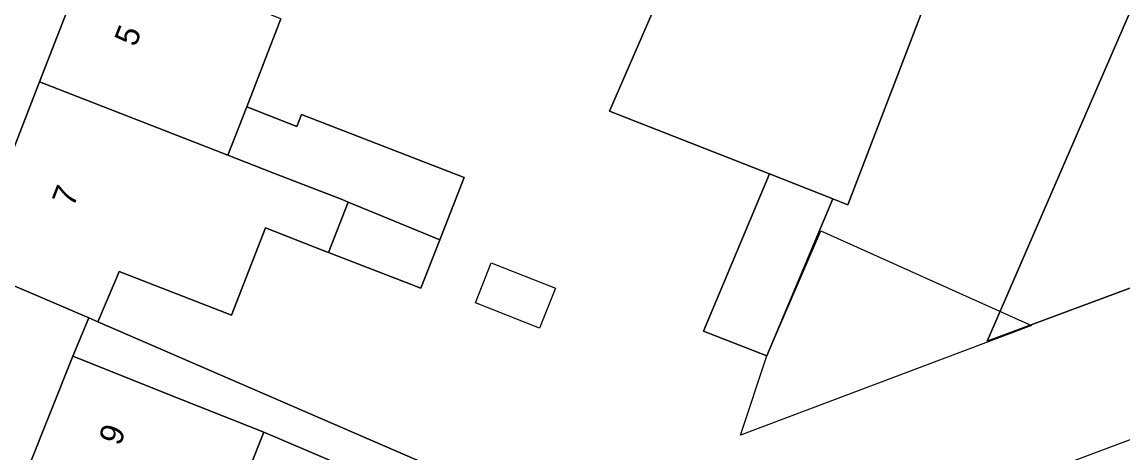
# Model space of a CAD drawing. Extents: x 161798 to 162385, y 382315 to 382833.
# Drawn here: x 162189.17 to 162235.92, y 382570.82 to 382589.12 of the extents above; entities that cross this region are included whole.
import ezdxf

# ---------------------------------------------------------------- set-up
doc = ezdxf.new("R2010")
doc.units = 0
for name, color, linetype in [('IMGEO_Erf', 7, 'Continuous'), ('IMGEO_Pand', 7, 'Continuous'), ('IMGEO_Pand_nummerreeks', 7, 'Continuous'), ('IMGEO_Pand_vergunning_verleend', 7, 'Continuous'), ('IMGEO_Voetpad_open', 7, 'Continuous')]:
    doc.layers.add(name, color=color, linetype=linetype)

msp = doc.modelspace()

# ---------------------------------------------------------------- linework, layer by layer
at = {"layer": 'IMGEO_Erf'}
for points in [[(162239.564, 382579.067), (162230.156, 382575.563), (162238.632, 382595.119), (162235.65, 382596.412), (162237.101, 382599.761)], [(162200.163, 382589.258), (162198.709, 382585.516), (162200.84, 382584.689), (162201.036, 382585.195), (162207.94, 382582.514), (162206.909, 382579.875), (162206.102, 382577.812), (162202.18, 382579.336), (162201.962, 382579.421), (162199.507, 382580.375), (162198.066, 382576.668), (162193.297, 382578.521), (162193.239, 382578.387), (162193.08, 382578.017), (162192.384, 382576.394), (162209.772, 382568.862)], [(162207.999, 382568.054), (162199.431, 382571.699), (162197.495, 382566.833)]]:
    msp.add_lwpolyline(points, dxfattribs=at)
msp.add_lwpolyline([(162220.802, 382574.936), (162218.113, 382575.994), (162220.912, 382582.668), (162214.119, 382585.338), (162217.707, 382593.617), (162218.951, 382596.487), (162224.575, 382594.142), (162225.75, 382596.93), (162229.557, 382595.219), (162227.423, 382589.653), (162224.244, 382581.359), (162223.602, 382581.611)], close=True, dxfattribs=at)
at = {"layer": 'IMGEO_Pand'}
for points in [[(162240.534, 382608.284), (162236.893, 382599.851), (162237.101, 382599.761), (162235.65, 382596.412), (162238.632, 382595.119), (162230.156, 382575.563), (162239.564, 382579.067), (162245.276, 382592.24), (162246.707, 382595.54), (162246.525, 382595.619), (162250.193, 382604.115)], [(162223.602, 382581.611), (162224.244, 382581.359), (162227.423, 382589.653), (162217.707, 382593.617), (162214.119, 382585.338), (162220.912, 382582.668)], [(162200.163, 382589.258), (162198.47, 382589.917), (162193.809, 382591.727), (162192.158, 382592.368), (162189.907, 382586.575), (162197.912, 382583.464), (162198.709, 382585.516)], [(162202.18, 382579.336), (162203.015, 382581.474), (162202.76, 382581.579), (162199.819, 382582.722), (162197.912, 382583.464), (162189.907, 382586.575), (162186.87, 382578.758), (162192.01, 382576.554), (162192.384, 382576.394), (162193.08, 382578.017), (162193.239, 382578.387), (162193.297, 382578.521), (162198.066, 382576.668), (162199.507, 382580.375), (162201.962, 382579.421)], [(162198.709, 382585.516), (162197.912, 382583.464), (162199.819, 382582.722), (162202.76, 382581.579), (162203.015, 382581.474), (162204.749, 382580.762), (162206.909, 382579.875), (162207.94, 382582.514), (162201.036, 382585.195), (162200.84, 382584.689)], [(162223.602, 382581.611), (162220.912, 382582.668), (162218.113, 382575.994), (162220.802, 382574.936)], [(162204.749, 382580.762), (162203.015, 382581.474), (162202.18, 382579.336), (162206.102, 382577.812), (162206.909, 382579.875)], [(162197.495, 382566.833), (162199.431, 382571.699), (162195.967, 382573.077), (162191.32, 382574.925), (162189.401, 382570.101)]]:
    msp.add_lwpolyline(points, close=True, dxfattribs=at)
at = {"layer": 'IMGEO_Pand_vergunning_verleend'}
for points in [[(162219.681, 382571.572), (162220.802, 382574.936), (162223.089, 382580.252), (162232.033, 382576.233)], [(162233.442, 382570.34), (162259.36, 382580.047), (162262.443, 382571.813), (162236.525, 382562.106)], [(162208.422, 382577.199), (162209.095, 382578.894), (162211.82, 382577.812), (162211.147, 382576.117)]]:
    msp.add_lwpolyline(points, close=True, dxfattribs=at)
at = {"layer": 'IMGEO_Voetpad_open'}
msp.add_lwpolyline([(162187.527, 382565.389), (162189.401, 382570.101), (162191.32, 382574.925), (162192.01, 382576.554), (162186.87, 382578.758), (162189.907, 382586.575), (162192.158, 382592.368), (162193.809, 382591.727), (162194.258, 382593.095), (162197.557, 382601.585), (162199.956, 382607.761), (162201.387, 382611.319), (162204.087, 382610.149), (162208.854, 382621.959), (162202.052, 382624.786), (162201.9, 382624.403), (162200.724, 382621.462)], dxfattribs=at)
msp.add_lwpolyline([(162192.384, 382576.394), (162192.01, 382576.554), (162191.32, 382574.925), (162195.967, 382573.077), (162199.431, 382571.699), (162207.999, 382568.054), (162208.629, 382567.001), (162209.683, 382564.212), (162210.529, 382561.972), (162211.377, 382559.731), (162212.223, 382557.492), (162213.07, 382555.252), (162213.679, 382553.641), (162215.209, 382554.209), (162213.74, 382558.168), (162211.387, 382564.51), (162210.278, 382567.499), (162209.772, 382568.862)], close=True, dxfattribs=at)

# ---------------------------------------------------------------- texts
at = {"layer": 'IMGEO_Pand_nummerreeks'}
for s, rotation, p in [('5', 68.7664, (162193.99, 382588.027)), ('7', 68.7664, (162191.346, 382581.222)), ('9', 68.3075, (162193.321, 382571.081))]:
    msp.add_text(s, height=1, rotation=rotation, dxfattribs=at).set_placement(p)

doc.saveas('drawing.dxf')
